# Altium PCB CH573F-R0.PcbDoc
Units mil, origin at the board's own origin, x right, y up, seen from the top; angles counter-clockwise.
Board outline 1477.48 x 1928.94 mil, 2 copper layers (Top Layer, Bottom Layer); 30 components, 39 nets, 160 pads, 180 vias.
Unrouted connection lines stored in the file: 1.
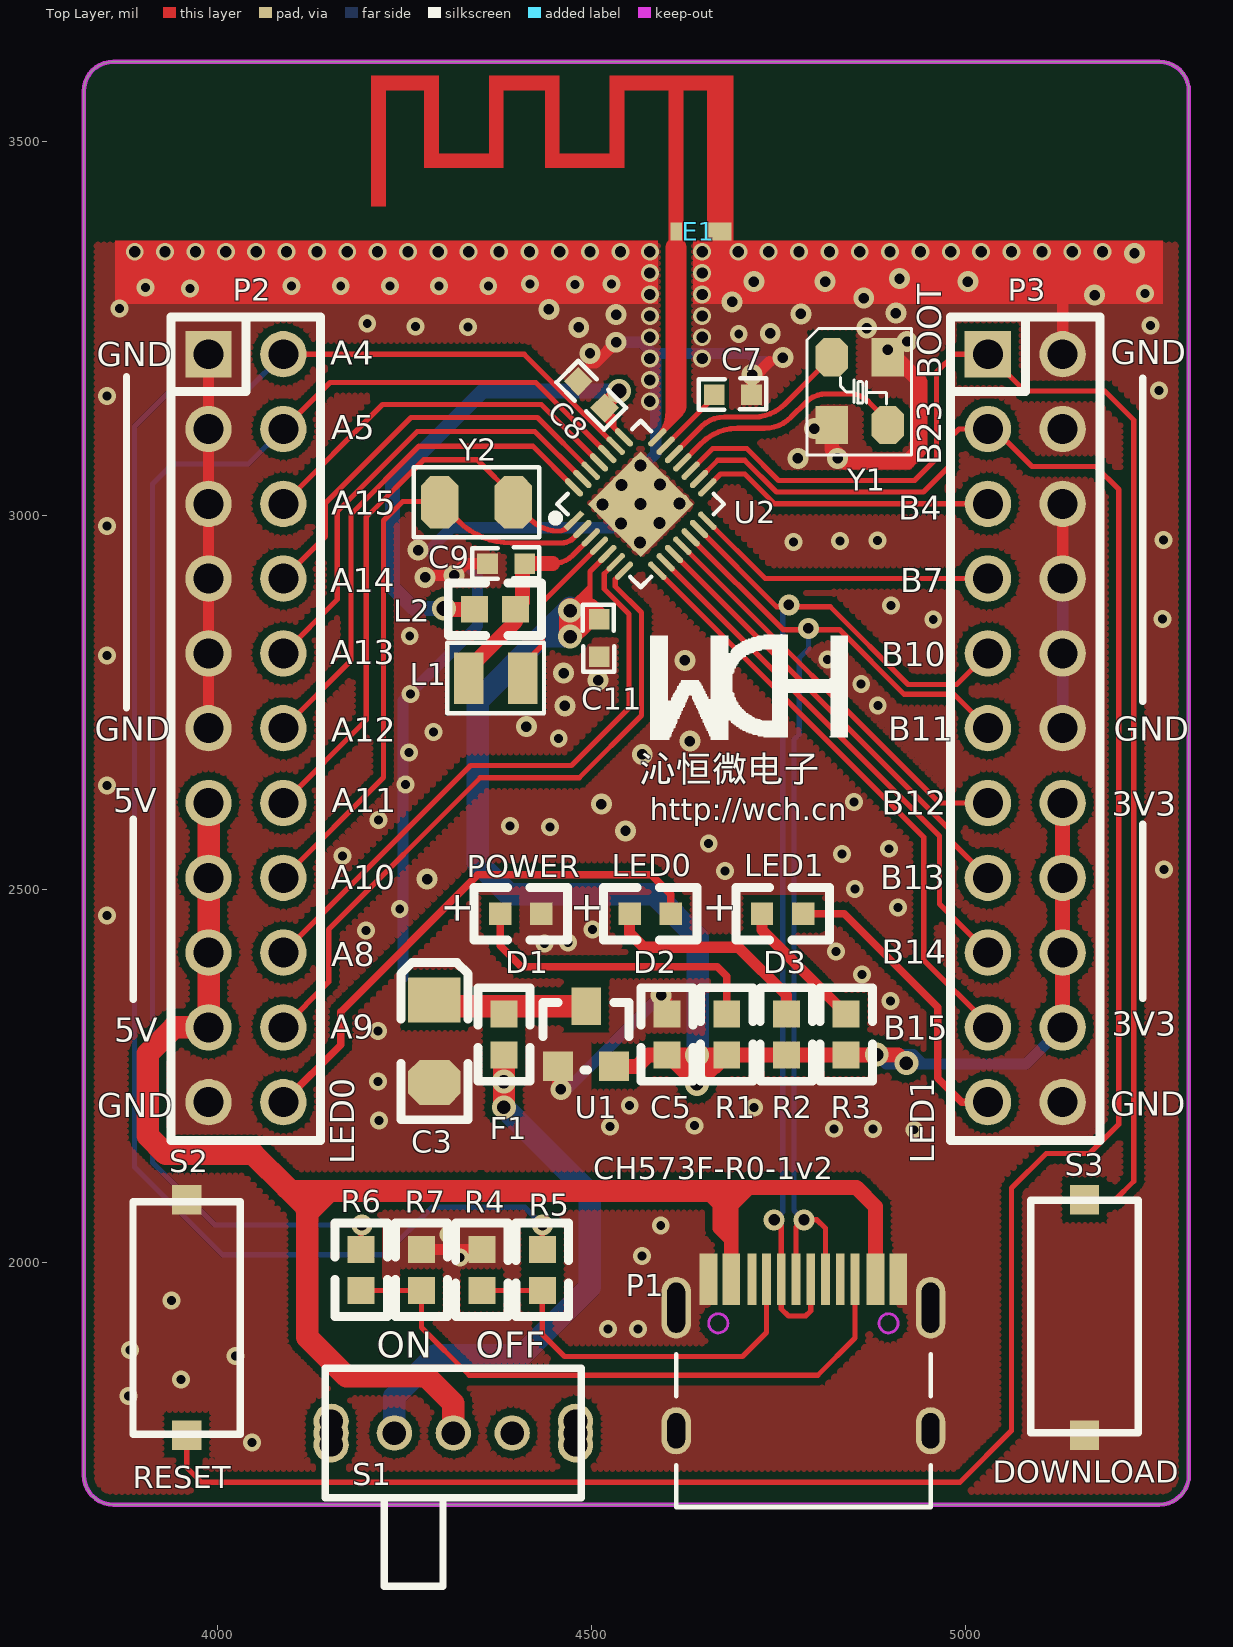
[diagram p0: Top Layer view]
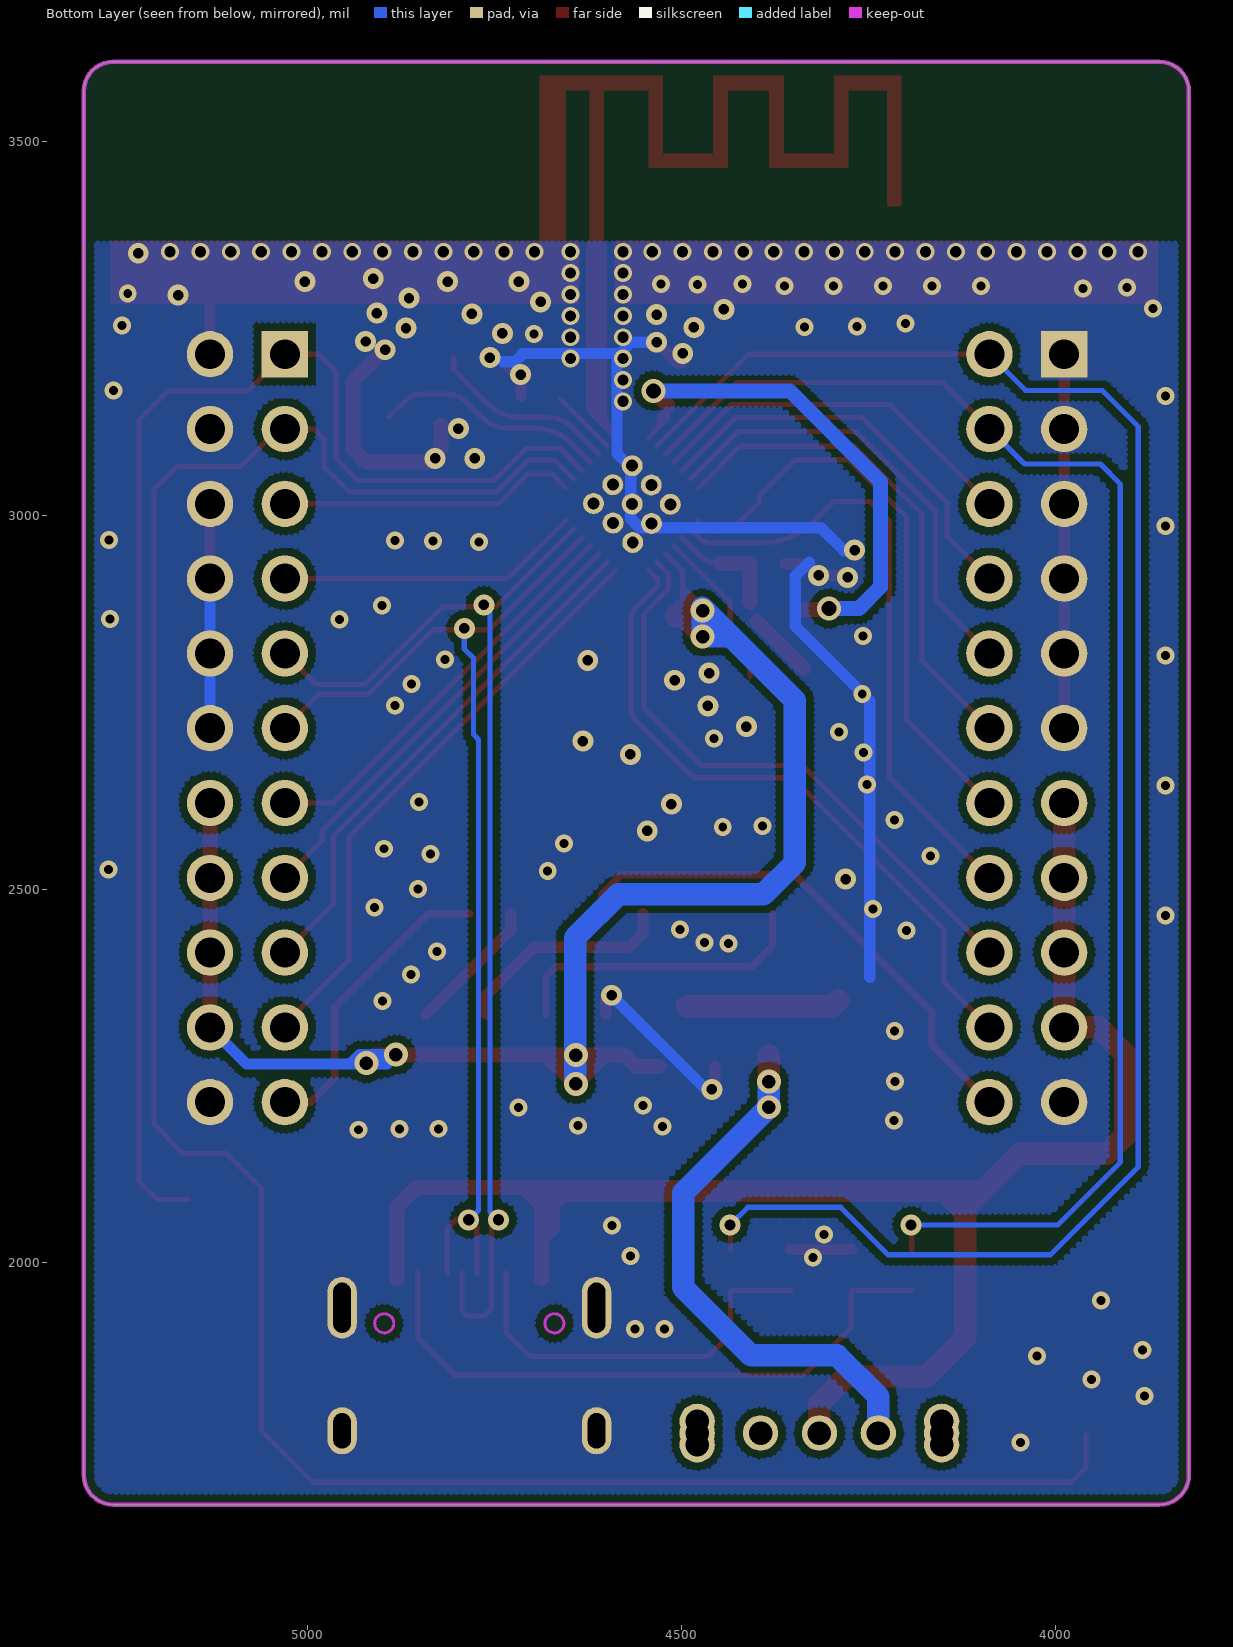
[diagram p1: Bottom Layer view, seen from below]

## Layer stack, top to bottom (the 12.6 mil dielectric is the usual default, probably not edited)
Top Solder: solder mask 0.4, Solder Resist, Dk 3.5
Top Layer: signal copper 1.4
Dielectric1: dielectric 12.6, FR-4, Dk 4.8
Bottom Layer: signal copper 1.4
Bottom Solder: solder mask 0.4, Solder Resist, Dk 3.5

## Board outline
3821.26,1716.37 ccw(c3860.63,1716.37) 3860.63,1677 5259.37,1677 ccw(c5259.37,1716.37) 5298.74,1716.37 5298.74,3566.57 ccw(c5259.37,3566.57) 5259.37,3605.94 3860.63,3605.94 ccw(c3860.63,3566.57) 3821.26,3566.57

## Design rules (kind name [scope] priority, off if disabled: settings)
Clearance Clearance_2 [InNamedPolygon('GNDAA')] p1: gap=6 ignorepadtopadclearanceinfootprint=FALSE except(0: Arc-Hole Track-Hole SMDPad-Hole THPad-Hole Via-Hole Fill-Hole Poly-Hole Region-Hole Text-Hole)
Clearance Clearance_3 [InPolygon] p2: gap=10 ignorepadtopadclearanceinfootprint=FALSE except(0: Arc-Hole Track-Hole SMDPad-Hole THPad-Hole Via-Hole Fill-Hole Poly-Hole Region-Hole Text-Hole)
Clearance [All] p3: gap=6 ignorepadtopadclearanceinfootprint=FALSE except(0: Arc-Hole Track-Hole SMDPad-Hole THPad-Hole Via-Hole Fill-Hole Poly-Hole Region-Hole Text-Hole)
ComponentClearance [All] p1 off: gap=10 collisioncheckmode=3 verticalgap=10 showdistances=FALSE
MinimumSolderMaskSliver [All] p1 off: minsoldermaskwidth=10
PolygonConnect [All] p1: connectstyle=Direct reliefconductorwidth=10 reliefentries=4 polygonreliefangle="90 Angle" airgapwidth=10
RoutingVias [All] p1: holewidth=12 width=24 viastyle="Through Hole" minholewidth=12 minwidth=24 maxholewidth=28 maxwidth=50
SilkToSilkClearance [All] p1 off: silktosilkclearance=10
SilkToSolderMaskClearance SilkscreenOverComponentPads [IsPad] p1 off: minsilkscreentomaskgap=10 clearancetoexposedcopper=TRUE
SolderMaskExpansion [All] p1 off: expansion=4 istentingtop=FALSE
Width [All] p1: maxlimit=50 minlimit=6 preferedwidth=7
26 further rules are at their usual default settings.

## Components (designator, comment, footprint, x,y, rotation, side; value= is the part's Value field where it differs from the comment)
C3 "10uF" 3216 4290,2351.5 r90 top
C5 "2.2uF" 0603 4601,2278 r90 top
C7 "1uF" 0402 4664,3161 r0 top
C8 "0.1uF" 0402 4517.62,3143.4 r135 top
C9 "2.2uF" 0402 4361,2935 r0 top
C11 "2.2uF" 0402 4510.15,2810.7 r90 top
D1 "POWER" 0603+ 4378,2466.87 r0 top
D2 "LED0" 0603+ 4551,2466.87 r0 top
D3 "LED0" 0603+ 4728,2466.87 r0 top
E1 "ANTENNA" ANT-F-1-2.4G-1.6 4613.3,3378.99 r0 top
F1 "500mA" 0603 4383,2278 r90 top
L1 "22uH" L2.2 4407.99,2782 r180 top
L2 "0Ω" 0603 4398.47,2874 r180 top
P1 "TYPE-C-Receptacle-2.0" TYPE-C-Receptacle-2.0 4783.33,1673.28 r0 top
P2 "Header 11X2H" IDC22 3988,3215 r0 top
P3 "Header 11X2H" IDC22 5030,3215 r0 top
R1 "1K" 0603 4680.82,2333 r270 top
R2 "1K" 0603 4760.63,2333 r270 top
R3 "1K" 0603 4840.45,2333 r270 top
R4 "5.1K" 0603 4353.52,1963.16 r90 top
R5 "NC(0R)" 0603 4434.31,1963.16 r90 top
R6 "NC(0R)" 0603 4191.95,2018.16 r270 top
R7 "5.1K" 0603 4272.74,2018.16 r270 top
S1 "SW" "Horizontal Slide Switch-8.7*4.4MM-2D" 4144,1686.02 r0 top
S2 "RST#" KEY-SMD-6.1*3.65*2.5 3958.85,2084.76 r270 top
S3 "Download" KEY-SMD-6.1*3.65*2.5 5159.15,1769.8 r90 top
U1 "6219P33M" SOT-23 4455,2263 r0 top
U2 "CH573F" QFN28_4X4 4476.65,2992.44 r315 top
Y1 "32MHz" 3225 4821.2,3120.45 r90 top
Y2 "32.768K" fc-135 4297.05,3017 r0 top (schematic designator Y1)

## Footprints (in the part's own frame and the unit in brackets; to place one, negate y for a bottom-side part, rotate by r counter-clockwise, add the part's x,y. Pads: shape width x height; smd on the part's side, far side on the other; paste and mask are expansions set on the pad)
0402 [mm]
  rect 0.7x0.7 smd: 1(0,0) 2(1.27,0)
  silkscreen extent -0.52,-0.51 1.76,0.55
0603 [mil]
  rect 36x36 smd: 1(0,0) 2(55,0)
  silkscreen extent -35,-35 90,35
0603+ [mil]
  rect 30x30 smd: 1(0,0) 2(55,0)
  silkscreen extent -35,-35 90,35
3216 [mil]
  rect 60x70 smd: 1(0,0)
  oct 60x70 smd: 2(-110,0)
  silkscreen extent -160,-45 50,45
3225 [mm]
  oct 1.3x1.1 smd: 1(2.3,0) 3(0,-1.9)
  rect 1.3x1.1 smd: 2(0,0) 4(2.3,-1.9)
  silkscreen extent -1.02,-2.7 3.27,0.84
ANT-F-1-2.4G-1.6 [mm]
  rect 0.8x0.6 smd mask+0: 0(1.483,0)
  rect 0.4x0.6 smd mask+0: 1(0,0)
  Top Layer region: -9.86,4.976 -10.36,4.976 -10.36,0.856 -9.86,0.856
  Top Layer region: -8.06,5.296 -10.36,5.296 -10.36,4.796 -8.06,4.796
  Top Layer region: -8.06,4.977 -8.56,4.977 -8.56,2.157 -8.06,2.157
  Top Layer region: -5.875,2.657 -8.364,2.657 -8.364,2.157 -5.875,2.157
  Top Layer region: -5.86,4.977 -6.36,4.977 -6.36,2.157 -5.86,2.157
  Top Layer region: -3.96,5.296 -6.36,5.296 -6.36,4.796 -3.96,4.796
  Top Layer region: -3.96,4.976 -4.46,4.976 -4.46,2.156 -3.96,2.156
  Top Layer region: -1.85,2.651 -4.39,2.651 -4.39,2.156 -1.85,2.156
  Top Layer region: -1.76,4.977 -2.26,4.977 -2.26,2.157 -1.76,2.157
  Top Layer region: 1.94,5.296 -2.26,5.296 -2.26,4.796 1.94,4.796
  Top Layer region: 1.94,5.002 1.04,5.002 1.04,-0.304 1.94,-0.304
  Top Layer region: 0.24,5.027 -0.26,5.027 -0.26,-0.304 0.24,-0.304
fc-135 [mil]
  oct 50x70 smd: 1(0,0) 2(98.43,0)
  silkscreen extent -35,-47 133,47
"Horizontal Slide Switch-8.7*4.4MM-2D" [mm]
  round 1.2 hole 0.8: 0(0.2,1.8) 0(0.2,2.2) 0(0.2,2.6) 0(8.5,1.8) 0(8.5,2.2) 0(8.5,2.6) 1(4.35,2.2) 2(2.35,2.2) 3(6.35,2.2)
  silkscreen extent 0,-3 8.7,4.4
IDC22 [mil]
  rect 62x62 hole 40: 1(0,0)
  round 62 hole 40: 2(100,0) 3(0,-100) 4(100,-100) 5(0,-200) 6(100,-200) 7(0,-300) 8(100,-300) 9(0,-400) 10(100,-400) 11(0,-500) 12(100,-500) 13(0,-600) 14(100,-600) 15(0,-700) 16(100,-700) 17(0,-800) 18(100,-800) 19(0,-900) 20(100,-900) 21(0,-1000) 22(100,-1000)
  silkscreen extent -50,-1051 150,50
KEY-SMD-6.1*3.65*2.5 [mm]
  rect 1x1 smd: 1(0,0) 2(8,0)
  silkscreen extent 0.08,-1.83 7.98,1.83
L2.2 [mm]
  rect 1x1.75 smd: 1(0,0) 2(1.833,0)
  silkscreen extent -0.72,-1.19 2.56,1.2
QFN28_4X4 [mm]
  rect 2.54x2.54 smd: 0(1.2,2)
  rect 0.2x0.8 smd: 1(0,0)
  oval 0.2x0.8 smd: 2(0.4,0) 3(0.8,0) 4(1.2,0) 5(1.6,0) 6(2,0) 7(2.4,0) 15(2.4,4) 16(2,4) 17(1.6,4) 18(1.2,4) 19(0.8,4) 20(0.4,4) 21(0,4)
  oval 0.8x0.2 smd: 8(3.2,0.8) 9(3.2,1.2) 10(3.2,1.6) 11(3.2,2) 12(3.2,2.4) 13(3.2,2.8) 14(3.2,3.2) 22(-0.8,3.2) 23(-0.8,2.8) 24(-0.8,2.4) 25(-0.8,2) 26(-0.8,1.6) 27(-0.8,1.2) 28(-0.8,0.8)
  silkscreen extent -0.8,-0.51 3.2,4
SOT-23 [mil]
  rect 40x40 smd: 1(0,0) 2(75,0)
  rect 40x50 smd: 3(38,80)
  silkscreen extent -20,-5 95,85
TYPE-C-Receptacle-2.0 [mm]
  oval 1x1.6 hole 0.6 slot 1.2 at 90 deg: 0(-4.32,2.6) 0(4.32,2.6)
  oval 1x2.1 hole 0.6 slot 1.7 at 90 deg: 0(-4.32,6.78) 0(4.32,6.78)
  rect 0.6x1.75 smd: A1(-3.225,7.75) A4(-2.45,7.75) B1(3.225,7.75) B4(2.45,7.75)
  rect 0.3x1.75 smd: A5(-1.25,7.75) A6(-0.25,7.75) A7(0.25,7.75) A8(1.25,7.75) B5(1.75,7.75) B6(0.75,7.75) B7(-0.75,7.75) B8(-1.75,7.75)
  Keep-Out Layer circle w0.1: c2.89,6.25 r0.325
  Keep-Out Layer circle w0.1: c-2.89,6.25 r0.325
  silkscreen extent -4.32,0 4.32,5.2

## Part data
C3 C5 C7 C8 C9 C11: library part CAP, "Capacitor"
D1: library part LED0, "Typical INFRARED GaAs LED"
D2 D3: "Typical INFRARED GaAs LED"
E1: "Generic Antenna"
F1: library part FUSE1, "Fuse"
L1 L2: library part INDUCTOR
P1: "Type-C USB2.0 母座"
P2 P3: "Header, 11-Pin, Dual row, Right Angle"
R1 R2 R3: library part RES
R4 R5 R6 R7: library part RES2
S2 S3: library part SW-PB, "Switch"
U2: "RISC-V MCU with BLE/USB/ADC/SPI/4*UART"
Y1: library part 晶体
Y2: library part XTAL, "Crystal Oscillator"

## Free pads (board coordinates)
  round 28 hole 16: 0(4514.58,3014.31) 0(4539.72,2988.73) 0(4540.07,3040.12) 0(4564.85,2963.15) 0(4565.55,3065.93) 0(4565.6,3014.68) 0(4591.12,2989.23) 0(4591.47,3040.62) 0(4617.4,3015.31)

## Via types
v1: diameter 24, hole 12, Top Layer to Bottom Layer, tented both sides, 81 vias
v2: diameter 24, hole 15, Top Layer to Bottom Layer, tented both sides, 44 vias
v3: diameter 28, hole 14, Top Layer to Bottom Layer, tented both sides, 41 vias
v4: diameter 32, hole 18, Top Layer to Bottom Layer, tented both sides, 8 vias
v5: diameter 28, hole 15, Top Layer to Bottom Layer, tented both sides, 4 vias
v6: diameter 32, hole 20, Top Layer to Bottom Layer, tented both sides, 2 vias

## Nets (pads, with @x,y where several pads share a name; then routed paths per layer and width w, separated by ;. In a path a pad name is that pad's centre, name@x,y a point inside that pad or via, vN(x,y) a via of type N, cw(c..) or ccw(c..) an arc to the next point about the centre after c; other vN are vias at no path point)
+3V3: C5.1 C11.2 P3.14 P3.16 P3.18 P3.20 R1.2 R2.2 R3.2 U1.2 U2.5 | length 2548.5
  Top Layer w7: 4496.64,2875.91 4497.85,2877.12 ; C11.2@4507.65,2861.42 4504.69,2864.37 4497.85,2871.21 4497.85,2873.36 4497.85,2877.12 ; U2.5 4497.85,2924.56 4497.85,2903.99 ; 4497.85,2877.12 4497.85,2897.82 ; 4497.85,2897.82 4474.3,2874.27 4471.49,2874.27 4471.49,2877.63 4497.85,2903.99 ; 4497.85,2897.82 4497.85,2903.99
  Top Layer w20: U1.2 4561,2263 4576,2278 C5.1 C5.1@4602.23,2278 ; v4(4920.94,2267.21) 4910.14,2278 4881.4,2278 R3.2 R2.2 R1.2 ; P3.20 P3.18 P3.16 P3.14 ; C5.1@4602.23,2278 v4(4640.84,2278.02) ; C5.1@4602.23,2278 C5.1@4617.46,2262.77 ; C5.1@4617.46,2262.77 v4@4640.84,2262.77 ; C5.1@4617.46,2262.77 v4(4640.84,2239.39) ; v4(4640.84,2239.39) R1.2@4664.23,2262.77 ; v4(4640.84,2239.39) v4@4640.84,2262.77 ; v4@4640.84,2262.77 R1.2@4664.23,2262.77 ; v4@4640.84,2262.77 v4(4640.84,2278.02) ; v4(4640.84,2278.02) R1.2@4679.45,2278 ; R1.2@4664.23,2262.77 4665.59,2262.77 R1.2 ; R1.2@4664.23,2262.77 R1.2@4679.45,2278 ; R1.2@4679.45,2278 R1.2
  Top Layer w30: v4(4471.49,2837.58) v4@4471.49,2839.58 ; v4@4471.49,2874.27 v4(4471.49,2872.27) v4@4471.49,2839.58 ; C11.2@4496.94,2874.27 4497.85,2873.36 4506.84,2864.37 4504.69,2864.37 4496.28,2864.37 4487.84,2855.93 v4@4471.49,2839.58
  Bottom Layer w15: P3.20 5081,2266 4942.53,2266 ; 4908.47,2278.47 4920.94,2278.47 4930.06,2278.47 4931.13,2277.4 4942.53,2266 ; 4908.47,2278.47 4920.33,2266.6 v4@4920.94,2266 ; 4908.47,2278.47 v4(4881.4,2278.47) 4893.87,2266 v4@4920.94,2266 ; v4@4920.94,2266 4942.53,2266
  Bottom Layer w30: v4(4471.49,2872.27) v4(4471.49,2837.58) 4433.47,2837.58 ; v4@4471.8,2875.91 4469.83,2873.93 4452.48,2856.59 4433.47,2837.58 ; v4(4640.84,2239.39) 4642,2240.55 4642,2278.02 4642,2435 4584,2493 4390,2493 4348,2535 4348,2752.11 4433.47,2837.58
+5V: P1.A4 P1.B4 P2.13 P2.15 P2.17 P2.19 S1.1 | length 3003.7
  Top Layer w20: 4092.77,2100.82 4116.88,2100.82 ; 4685.21,2033.73 4672.03,2046.91 4672.03,2078.32 4658.7,2091.66 ; P1.A4 4686.87,2077.34 ; P1.B4 4879.79,2075.24 4854.21,2100.82 4710.35,2100.82 ; 4116.88,2076.7 4140.99,2100.82 ; 4116.88,2076.7 4116.88,2100.82 ; 4116.88,2076.7 4116.88,2057.42 4120.2,2060.74 4151.12,2091.66 4658.7,2091.66 ; 4116.88,2100.82 4140.99,2100.82 ; 4140.99,2100.82 4649.54,2100.82 ; 4649.54,2100.82 4665.55,2100.82 ; 4649.54,2100.82 4658.7,2091.66 ; 4665.55,2100.82 4686.87,2079.5 ; 4665.55,2100.82 4676.08,2100.82 ; 4676.08,2100.82 4686.87,2090.02 4686.87,2079.5 ; 4676.08,2100.82 4710.35,2100.82 ; 4686.87,2077.34 4710.35,2100.82 ; 4686.87,2077.34 4686.87,2079.5
  Top Layer w30: P2.13 P2.15 P2.17 P2.19 3941.74,2315 3906.46,2279.72 3906.46,2170.34 3930.79,2146.01 4047.58,2146.01 4092.77,2100.82 4116.88,2076.7 4120.2,2073.39 4120.2,2060.74 4120.2,1900.46 4172.42,1848.23 4279.41,1848.23 4315.26,1812.39 S1.1
ANT: E1.1 U2.21 | length 370.9
  Top Layer w7: 4602.47,3153.76 4602.47,3138.72 cw(c4553.08,3138.72) U2.21 ; 4610.29,3142.04 cw(c4571.76,3142.04) 4599,3114.79 U2.21 ; 4623.64,3148.23 cw(c4602.41,3148.23) 4617.42,3133.22 U2.21
  Top Layer w28.1: 4613,3145 4613,3358
BOOT: P3.1 S3.2 U2.17 | length 1890.3
  Top Layer w7: U2.17 4662.12,3088.83 4707.49,3088.83 4750.12,3046.2 4932.05,3046.2 4961.32,3075.47 4961.32,3191.27 4985.05,3215 P3.1 5079.16,3165.84 5186.19,3165.84 5225.04,3126.99 5225.04,2109.34 5200.46,2084.76 S3.2
GND: C3.2 C5.2 C7.2 C8.2 C9.1 C11.1 D1.2 E1.0 P1.0 P1.A1 P1.B1 P2.1 P2.3 P2.5 P2.7 P2.9 P2.11 P2.21 P3.2 P3.4 P3.6 P3.8 P3.10 P3.12 P3.22 pad.0 R4.2 R7.1 S2.1 S3.1 U1.1 U2.0 Y1.2 Y1.4 | length 3089.3
  Top Layer w15: P2.11 P2.9 P2.7 P2.5 P2.3 P2.1 ; R7.1 4312.69,2018.16 ; v3(4277.49,2916.57) 4280.28,2919.35 v3(4316.28,2919.35) 4331.93,2935 C9.1 ; 4316.19,2018.16 4312.69,2018.16 ; R4.2 4324.14,2018.16 4312.69,2018.16 ; U1.1 4455,2236 v3(4459,2232) ; v3@4499.64,3203.36 4505.36,3203.36 4508,3206 v3(4533,3231) ; v3(4593,2358) 4601,2350 C5.2 ; C7.2@4714,3159 C7.2 4714,3181 4717.68,3184.68 4738,3205 ; P3.8 P3.6 ; P3.2 5130,3309.95 5134.94,3314.89
  Top Layer w20: Y1.2 4821.2,3115.45 4821.2,3088.56 4831.52,3078.23 4838.77,3070.99 4922.24,3070.99 4939.09,3087.84 4939.09,3178.11 Y1.4@4907.94,3209.26
  Top Layer w30: 5150,3322.94 5151.85,3324.78
  Bottom Layer w15: 4248,2382 4248,2473.06 4248,2639.9 4248,2682.62 4248,2751 ; v1(4258,2761) 4248,2751 ; v3@4282,2952 4313,2983 4539.72,2983 4555.43,2983 4567.5,2995.07 4567.5,3014.68 4567.5,3064 4586,3082.5 4586,3152 4586,3180.57 4586,3209.14 v2@4586,3214 ; 4329,2937 4331.46,2934.54 4347.7,2918.3 4347.7,2851.7 4257.5,2761.5 4248,2752 4248,2751 ; v3(4459,2232) 4467,2232 v3(4593,2358) ; v3(4533,3231) 4567,3231 4569.14,3228.86 4582,3216 4648,3216 4713,3216 ; 4713,3214 4722,3205 4738,3205 ; P3.12 P3.10 P3.8
  other v1: 4046.26,1759.9 3880.8,1822.38 3951.38,1844.36 4024.28,1875.6 3883.11,1883.7 4522.32,1912.02 4562.12,1912.02 3938.65,1949.66 4324.14,2007.29 4567.71,2009.65 4308.96,2038.27 4592.59,2050.06 4931.5,2178.15 4824.27,2179.46 4876.58,2179.13 4524.9,2182.29 4637.92,2183.52 4215.79,2190.42 4717.39,2208.14 4551.13,2210.68 4214.39,2242.87 4214.58,2310.1 4899.67,2350.24 4861.38,2385.86 4826.79,2416.62 4437.05,2427.32 4468.63,2428.67 4198.66,2444.82 4501.56,2445.95 3852.52,2464.82 4243.65,2473.06 4910.04,2475.19 4852,2500 4678.51,2524.33 5265.48,2525.85 4167,2544 4835,2547 4897.64,2553.84 4656.75,2560.83 4444.5,2582.91 4391.34,2584.25 4215,2592 4850.89,2616.04 3852.52,2638.37 4251.5,2639.9 4256.18,2682.62 4456.2,2700.96 4288.92,2709.9 4882.75,2745.53 4860.63,2774.29 4815.84,2807.04 3852.52,2811.92 4257,2838 4956.92,2860.46 5263.57,2860.89 4900.32,2879.04 4770.19,2964.08 4832,2965 4882.61,2965.77 5264.85,2966.82 3852.52,2985.48 3852.52,3159.03 5258.91,3166.38 4696.88,3241.87 4335.1,3251.33 4264.84,3251.89 5247.55,3253.18 4200.19,3255.82 3869,3276 5240,3296 3963,3303 3904,3304 4099,3306 4164.75,3306 4230.5,3306 4296.25,3306 4362,3306 4478,3308 4418,3309 4527,3309
  other v2: 4578,3152 4578,3180.57 4578,3209.14 4648,3209.14 4578,3237.71 4648,3237.71 4578,3266.29 4648,3266.29 4578,3294.86 4648,3294.86 4578,3323.43 4648,3323.43 3889.34,3352 3929.93,3352 3970.52,3352 4011.1,3352 4051.69,3352 4092.28,3352 4132.87,3352 4173.46,3352 4214.05,3352 4254.64,3352 4295.23,3352 4335.82,3352 4376.41,3352 4417,3352 4457.58,3352 4498.17,3352 4538.76,3352 4578,3352 4648,3352 4696.31,3352 4736.9,3352 4777.48,3352 4818.07,3352 4858.66,3352 4899.25,3352 4939.84,3352 4980.43,3352 5021.02,3352 5061.61,3352 5102.2,3352 5142.79,3352 5183.38,3352
  other v3: 4280.12,2513.31 4545.46,2577.68 4513.19,2613.54 4567.9,2680.09 4631.46,2697.62 4413,2717 4464.39,2744.8 4508.97,2779.14 4462.81,2788.55 4624.99,2805.58 4268.18,2953.2 4776.06,3075.81 4828.97,3075.69 4798,3115.45 4714.68,3187.68 4755.78,3210.38 4498,3216 4896,3221 4922,3232 4739,3243 4868,3250 4483,3251 4533,3268 4780,3269 4907,3270 4443,3275 4688,3285 4864,3290 5172.6,3294 4717,3312 4812.4,3312 5003.2,3312 4911.8,3316 5226,3350
LED0: D2.2 P2.22 | length 706.5
  Top Layer w10: P2.22 4165.07,2292.07 4165.07,2335.9 4348.17,2519 4580,2519 4606,2493 D2.2
LED1: D3.2 P3.21 | length 406.9
  Top Layer w10: D3.2 4838.02,2466.87 4963.05,2341.84 4963.05,2247.05 4995.1,2215 P3.21
NetD1_1: D1.1 R1.1 | length 412.8
  Top Layer w10: D1.1 4378,2424 4406,2396 4668,2396 4680.82,2383.18 R1.1
NetD2_1: D2.1 R2.1 | length 294.9
  Top Layer w15: D2.1 4551,2441 4570,2422 4696.68,2422 4760.63,2358.05 R2.1
NetD3_1: D3.1 R3.1 | length 180.5
  Top Layer w15: D3.1 4728,2445.45 R3.1
NetF1_1: F1.1 S1.2 | length 761.6
  Top Layer w30: v4(4382.94,2208.23) 4383,2208.28 v4@4383,2241.6 ; F1.1 v4@4383,2241.6 ; v4@4383.06,2241.54 v4@4383,2241.6
  Bottom Layer w30: S1.2 4236.52,1821.48 4291.57,1876.53 4406.46,1876.53 4497.45,1967.53 4497.45,2093.71 4383.06,2208.11 v4@4383.06,2241.54
  other v4: 4382.94,2242.54
NetP1_A5: P1.A5 R4.1 R5.1 | length 544.2
  Top Layer w7: R4.1 R5.1 4434.31,1904.56 4464.04,1874.83 4701.82,1874.83 4734.12,1907.13 P1.A5@4734.12,1986.39
NetP1_B5: P1.B5 R6.2 R7.2 | length 843.4
  Top Layer w7: R6.2 R7.2 4272.74,1913.84 4336.65,1849.92 4802.55,1849.92 4852.23,1899.6 P1.B5@4852.23,1986.39
PA4: P2.2 R5.2 U2.23 | length 2386.8
  Top Layer w7: P2.2 4409.99,3215 U2.23 ; R5.2 4434.31,2050.31 v5(4434.68,2050.69)
  Bottom Layer w7: P2.2 4039.43,3166.43 3937.22,3166.43 3889.03,3118.24 3889.03,2128.54 4006.5,2011.08 4223.47,2011.08 4286.77,2074.37 4410.99,2074.37 v5(4434.68,2050.69)
PA5: P2.4 R6.1 U2.24 | length 1958.6
  Top Layer w7: P2.4 4150.24,3177.24 4425.48,3177.24 U2.24 ; R6.1 4191.95,2049.73 v5(4192.92,2050.69)
  Bottom Layer w7: P2.4 4041.09,3068.09 3939.68,3068.09 3913.13,3041.55 3913.13,2134.22 3996.66,2050.69 v5(4192.92,2050.69)
PA8: P2.18 U2.6 | length 832.4
  Top Layer w7: P2.18@4068,2415 P2.18 4338.13,2665.13 4473.18,2665.13 4550.21,2742.16 4550.21,2867.87 4517.01,2901.07 4517.01,2921.45 U2.6
PA9: P2.20 U2.7 | length 905.7
  Top Layer w7: P2.20 4148.61,2375.61 4148.61,2446.03 4351.33,2648.74 4483.61,2648.74 4566.75,2731.88 4566.75,2869.72 4531.83,2904.63 4531.83,2913.99 U2.7
PA10: P2.16 U2.2 Y2.1 | length 838.3
  Top Layer w7: P2.16 4221.95,2648.95 4221.95,2992.61 4247.57,3018.23 4295.82,3018.23 Y2.1 4322.1,2991.94 ccw(c4392.81,3062.66) 4392.81,2962.66 4459.65,2962.66 ccw(c4459.65,2985.55) 4475.83,2969.35 ; 4473.48,2967 4475.83,2969.35 ; U2.2 4475.83,2969.35
PA11: P2.14 U2.1 Y2.2 | length 789.6
  Top Layer w7: P2.14 4198.84,2725.84 4198.84,2997.09 4275.54,3073.78 4347.58,3073.78 4395.47,3025.89 Y2.2 4418.75,2993.72 ccw(c4455.26,3030.23) 4455.26,2978.6 ccw(c4455.26,2996.84) U2.1@4468.14,2983.93 ; 4464.83,2980.62 U2.1@4468.14,2983.93 ; U2.1 U2.1@4468.15,2983.94
PA12: P2.12 U2.28 | length 682.3
  Top Layer w7: P2.12 4178.39,2805.39 4178.39,3001.02 4269.44,3092.08 4421.55,3092.08 U2.28
PA13: P2.10 U2.27 | length 618
  Top Layer w7: P2.10 4160.02,2887.02 4160.02,3004.79 4266.95,3111.73 4424.18,3111.73 U2.27
PA14: P2.8 U2.26 | length 555.9
  Top Layer w7: P2.8 4144.32,2971.32 4144.32,3016.06 4258.76,3130.5 4427.67,3130.5 U2.26
PA15: P2.6 U2.25 | length 509
  Top Layer w7: P2.6 4220.7,3147.7 4432.74,3147.7 U2.25
PB4: P3.5 U2.15 | length 399
  Top Layer w7: U2.15 4672.57,3054.74 4704.81,3054.74 4744.55,3015 P3.5
PB7: P3.7 U2.14 | length 407.3
  Top Layer w7: U2.14 4732.26,2915 P3.7
PB10: P1.A7 P1.B7 P3.9 U2.13 | length 1536.5
  Top Layer w7: U2.13 4747.53,2877.46 4763.99,2877.46 4819.3,2877.46 4923.39,2773.36 4988.36,2773.36 P3.9 ; v5@4745.3,2057.71 4753.8,2049.21 P1.B7 4753.8,1938.67 4763.47,1929 4786.35,1929 4793.17,1935.82 P1.A7 P1.A7@4793.17,1986.39
  Bottom Layer w7: v5@4745.3,2057.71 4755.64,2068.05 4755.64,2869.1 v3@4764,2877.46
  other v3: 4763.99,2880
  other v5: 4744.3,2057.71
PB11: P1.A6 P1.B6 P3.11 U2.12 | length 1476.6
  Top Layer w7: U2.12 4755.96,2846.76 4790.04,2846.76 4831.61,2846.76 4918.01,2760.36 4984.64,2760.36 P3.11 ; P1.A6@4773.49,1986.39 4773.49,2047.97 4783.23,2057.71 v5(4784.23,2057.71) 4801.64,2057.71 4812.86,2046.49 P1.B6@4812.86,1986.39
  Bottom Layer w7: v5@4783.23,2057.71 4770.9,2070.04 4770.9,2700.03 4777.74,2706.87 4777.74,2808.73 4790.04,2821.03 v3(4790.04,2848.42)
PB12: P3.13 U2.11 | length 551.1
  Top Layer w7: U2.11 4965.44,2615 P3.13
PB13: P3.15 U2.10 | length 606.8
  Top Layer w7: U2.10 4980.02,2578.15 4980.02,2564.98 P3.15
PB14: P3.17 U2.9 | length 700.2
  Top Layer w7: U2.9 4965.17,2570.73 4965.17,2479.83 P3.17
PB15: P3.19 U2.8 | length 793.7
  Top Layer w7: U2.8 4944.08,2569.55 4944.08,2405.29 5030,2319.37 P3.19
PB23: P3.3 S2.2 U2.16 | length 3224.7
  Top Layer w7: S2.2 3958.85,1726.68 3978.65,1706.87 4992.67,1706.87 5061.65,1775.86 5061.65,2100.04 5108.1,2146.48 5165.91,2146.48 5205.07,2185.64 5205.07,3034.11 5174.15,3065.03 5088.9,3065.03 P3.3@5038.93,3115 ; U2.16 4668.72,3073.16 4704.77,3073.16 4747.22,3030.71 4943.81,3030.71 4977.5,3064.4 4977.5,3101.3 4991.2,3115 P3.3 P3.3@5038.93,3115 ; P3.3@5050,3115 P3.3@5038.93,3115
V5V: C3.1 F1.2 U1.3 | length 206.5
  Top Layer w30: C3.1 4298.5,2343 U1.3
VDCIA: C8.1 L2.2 U2.22 | length 755.1
  Top Layer w7: C8.1@4517.62,3146.65 C8.1 ; C8.1@4518.62,3143.4 C8.1 ; v6@4535,3168 v6@4535,3177 ; U2.22 4529.62,3117.63 ; C8.1@4517.62,3137.4 4517.62,3129.63 4529.62,3117.63 ; C8.1@4517.62,3137.4 4529.62,3125.4 ; C8.1@4517.62,3137.4 C8.1 ; C8.1 4529.62,3131.4 4529.62,3125.4 ; 4529.62,3117.63 4529.62,3125.4
  Top Layer w20: v6(4302.69,2874.97) ccw(c4305.04,2877.33) 4305.04,2874 L2.2 ; C8.1@4517.62,3146.65 v6(4537,3166.03)
  Bottom Layer w20: v6(4302.69,2874.97) 4262.47,2874.97 4233.76,2903.69 4233.76,3044.76 4355.03,3166.03 v6(4537,3166.03)
VDCID: C9.2 L1.2 L2.1 U2.3 | length 240.9
  Top Layer w7: 4448.19,2935 ccw(c4448.19,2972.57) 4474.76,2946 U2.3
  Top Layer w20: L1.2@4335.83,2794.83 L2.1@4398.47,2857.47 ; L2.1@4408,2883.53 C9.2@4408,2935 ; C9.2 4448.19,2935
VINTA: C7.1 U2.20 | length 88.2
  Top Layer w7: U2.20 C7.1@4661.54,3155.06
VSW: L1.1 U2.4 | length 217.3
  Top Layer w7: L1.1@4407.99,2784 4407.99,2800 4434.45,2826.46 4434.45,2883.43 U2.4
X32MI: U2.19 Y1.1 | length 253.1
  Top Layer w7: U2.19 4647,3118.25 cw(c4677.78,3087.47) 4677.78,3131 4716.96,3131 ccw(c4716.96,3189.04) 4757.97,3147.97 4804.2,3194.2 Y1.1@4804.2,3211
X32MO: U2.18 Y1.3 | length 312.2
  Top Layer w7: U2.18 4647.17,3096.14 cw(c4695.1,3048.21) 4695.1,3116 4731,3116 ccw(c4731,3166.7) 4766.85,3130.85 4786.69,3150.69 cw(c4814,3123.37) 4814,3162 4845.86,3162 cw(c4845.86,3127.86) 4869.98,3152.02 Y1.3@4891,3131
pads on no net: P1.A8 P1.B8 S1.0 S1.3

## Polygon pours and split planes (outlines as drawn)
GND on Top Layer "GND" (hatched 90Degree grid 8 track 8, remove dead copper, pour order 5): 3824.05,3362 5320.24,3362 5321,3361.21 5321,1670 3822.26,1670
GND on Top Layer "GNDAA" (hatched 90Degree grid 8 track 8, remove dead copper, pour order 6): 4488,3363 4488,3088.26 4489.02,3087.24 4697.43,3087.24 4697.43,3356.74 4703.67,3363
GND on Bottom Layer "GND" (hatched 90Degree grid 8 track 8, remove dead copper, pour order 4): 3824.05,3363 5320.24,3363 5321,3362.21 5321,1670 3822.26,1670

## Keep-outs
Keep-Out Layer:
  the board outline again, w6

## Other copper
Top Layer:
  rectangle net GND: 4635.86,3282 5263.95,3367.02
  rectangle net GND: 3862.66,3282 4589,3367.02
  pour cut-out: 4303.75,2826.12 4304.61,2825.26 4304.61,2730.67 4435.61,2730.67 4440.63,2730.67 4440.61,2731.67 4440.61,2826.34

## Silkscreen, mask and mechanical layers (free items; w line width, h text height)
Top Overlay:
  drawing of 5 lines, arcs and shapes, not listed
  text "GND" at 5194.35,3201.81 h32
  text "A4" at 4150.52,3200.68 h32
  text "GND" at 3838.73,3198.6 h32
  text "BOOT" at 4967.58,3182.23 h32 r90
  text "A5" at 4152.35,3101.31 h32
  text "B23" at 4967.58,3066.84 h32 r90
  text "A15" at 4152.35,3000.11 h32
  text "B4" at 4909.89,2993.76 h32
  text "A14" at 4150.52,2897.07 h32
  text "B7" at 4913.09,2896.96 h32
  text "A13" at 4150.52,2800.75 h32
  text "B10" at 4887.45,2797.59 h32
  text "GND" at 3835.72,2698.07 h32
  text "B11" at 4896.43,2698.23 h32
  text "GND" at 5198.01,2697.98 h32
  text "A12" at 4151.74,2697.11 h32
  text "沁恒微电子" at 4564.49,2631.08 h60
  text "A11" at 4152.96,2602.61 h32
  text "5V" at 3860.87,2602.32 h32
  text "B12" at 4888.09,2599.5 h32
  text "3V3" at 5195.45,2598.15 h32
  text "http://wch.cn" at 4577.79,2582 h50
  text "LED0" at 4527,2517 h30
  text "LED1" at 4704,2517 h30
  text "POWER" at 4333,2516 h30
  text "A10" at 4151.13,2499.58 h32
  text "B13" at 4886.32,2499.88 h32
  text "B14" at 4888.09,2400.13 h32
  text "A8" at 4151.74,2396.55 h32
  text "3V3" at 5195.45,2303.78 h32
  text "A9" at 4150.52,2299.61 h32
  text "B15" at 4890.02,2298.2 h32
  text "5V" at 3862.25,2295.75 h32
  text "GND" at 5193.75,2197.13 h32
  text "GND" at 3839.05,2194.89 h32
  text "LED0" at 4182.83,2131.96 h32 r90
  text "LED1" at 4958.18,2132.41 h32 r90
  text "CH573F-R0-1v2" at 4502.67,2112.15 h30
  text "ON" at 4213.2,1873.37 h35
  text "OFF" at 4345.05,1873.37 h35
  text "DOWNLOAD" at 5036.71,1706.01 h30
  text "RESET" at 3886.94,1698.57 h30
